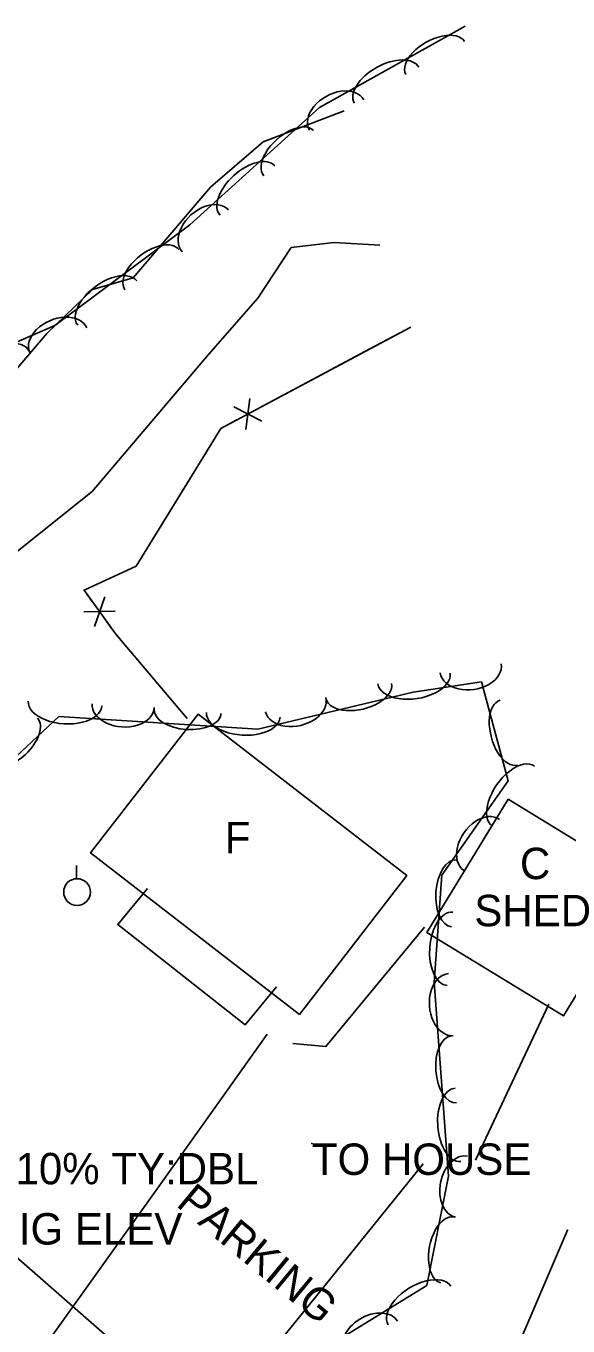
# Model space of a CAD drawing. Extents: x 1441650 to 1491889, y 345904 to 358319.
# Drawn here: x 1444391.3 to 1444477.5, y 355635.2 to 355842.2 of the extents above; entities that cross this region are included whole.
import ezdxf

# ---------------------------------------------------------------- set-up
doc = ezdxf.new("R2010")
doc.units = 0
for name, color, linetype in [('S_BUILDING', 7, 'Continuous'), ('S_BUILDING_ANNOT', 7, 'Continuous'), ('S_CROSS_DRAIN_ANNOT', 7, 'Continuous'), ('S_FENCE', 7, 'Continuous'), ('S_GRAVEL_ROAD', 7, 'Continuous'), ('S_MSC_PT_SYM', 7, 'Continuous'), ('S_PARKING', 7, 'Continuous'), ('S_PARKING_ANNOT', 7, 'Continuous'), ('S_SANITARY_SEWER', 7, 'Continuous'), ('S_SECONDARY_CTL_ANNOT', 7, 'Continuous'), ('S_SIDEWALK', 7, 'Continuous'), ('S_STREAM', 7, 'Continuous'), ('S_SURVEY_TEXT_ANNOT', 7, 'Continuous'), ('S_TREE', 7, 'Continuous'), ('S_UTILITY_POLE', 7, 'Continuous')]:
    doc.layers.add(name, color=color, linetype=linetype)

msp = doc.modelspace()

# ---------------------------------------------------------------- linework, layer by layer
at = {"layer": 'S_BUILDING'}
for points in [[(1444418.69, 355732.62), (1444451.91, 355706.91), (1444434.81, 355684.82), (1444401.59, 355710.53)], [(1444468.03, 355719.06), (1444489.77, 355705.76), (1444476.81, 355684.57), (1444455.07, 355697.86)]]:
    msp.add_lwpolyline(points, close=True, dxfattribs=at)
at = {"layer": 'S_FENCE'}
for p, q in [((1444426.3, 355777.92), (1444426.9, 355782.88)), ((1444424.37, 355781.53), (1444428.83, 355779.27)), ((1444402.2, 355746.58), (1444403.84, 355751.3)), ((1444405.51, 355748.99), (1444400.52, 355748.89)), ((1444477.43, 355650.46), (1444449.11, 355584.29))]:
    msp.add_line(p, q, dxfattribs=at)
for points in [[(1444416.95, 355731.95), (1444405.62, 355745.35), (1444400.54, 355752.36), (1444408.83, 355756.16), (1444422.3, 355778.11), (1444452.51, 355794.22)], [(1444446.01, 355790.76), (1444452.51, 355794.22)], [(1444428.37, 355781.35), (1444446.01, 355790.76)], [(1444413.34, 355763.52), (1444422.3, 355778.11), (1444424.84, 355779.46)], [(1444401.85, 355750.55), (1444400.54, 355752.36), (1444408.83, 355756.16), (1444413.34, 355763.52)], [(1444416.95, 355731.95), (1444405.62, 355745.35), (1444404.19, 355747.33)]]:
    msp.add_lwpolyline(points, dxfattribs=at)
at = {"layer": 'S_GRAVEL_ROAD'}
for points in [[(1444358.59, 355612.22), (1444371.41, 355616.19), (1444383.51, 355622.5), (1444395.16, 355633.2), (1444403.8, 355645.32), (1444412.43, 355657.43), (1444421.07, 355669.55), (1444429.7, 355681.67)], [(1444454.48, 355661.03), (1444439.8, 355642.84), (1444425.11, 355624.65), (1444410.77, 355628.2), (1444400.86, 355624.41), (1444394.09, 355619.51), (1444383.13, 355609.65), (1444378.74, 355594.44)]]:
    msp.add_lwpolyline(points, dxfattribs=at)
at = {"layer": 'S_MSC_PT_SYM'}
for points in [[(1444436.79, 355664.26), (1444436.79, 355664.31), (1444436.79, 355664.26), (1444436.74, 355664.26), (1444436.79, 355664.26), (1444436.79, 355664.21), (1444436.79, 355664.26), (1444436.84, 355664.26)], [(1444477.43, 355650.46), (1444477.43, 355650.51), (1444477.43, 355650.46), (1444477.38, 355650.46), (1444477.43, 355650.46), (1444477.43, 355650.41), (1444477.43, 355650.46), (1444477.48, 355650.46)]]:
    msp.add_lwpolyline(points, dxfattribs=at)
at = {"layer": 'S_PARKING'}
for points in [[(1444454.7, 355698.68), (1444439.01, 355679.71), (1444433.76, 355680.18)], [(1444462.8, 355661.63), (1444474.51, 355686.42)]]:
    msp.add_lwpolyline(points, dxfattribs=at)
at = {"layer": 'S_SANITARY_SEWER'}
msp.add_line((1444279.33, 355742.27), (1444417.64, 355621.87), dxfattribs=at)
at = {"layer": 'S_SIDEWALK'}
msp.add_lwpolyline([(1444431.17, 355689.19), (1444426.19, 355683.17), (1444405.9, 355699.12), (1444410.66, 355704.88)], dxfattribs=at)
at = {"layer": 'S_STREAM'}
for points in [[(1444441.93, 355828.65), (1444429.04, 355823.72), (1444420.65, 355816.52), (1444408.37, 355802.07), (1444401.88, 355800.24), (1444394.64, 355793.25), (1444389.5, 355787.19), (1444381.75, 355780.67), (1444366.63, 355772.48), (1444357.59, 355763.93), (1444355, 355760.85), (1444356.46, 355756.48), (1444352.71, 355749.61), (1444349.23, 355745.43)], [(1444362.43, 355740.87), (1444369.13, 355746.99), (1444380.64, 355751.13), (1444401.82, 355768.08), (1444408.39, 355775.83), (1444420.35, 355789.89), (1444428.21, 355798.87), (1444433.51, 355806.91), (1444440.33, 355807.72), (1444447.6, 355807.28)]]:
    msp.add_lwpolyline(points, dxfattribs=at)
at = {"layer": 'S_TREE'}
msp.add_lwpolyline([(1444439.99, 355632.37), (1444455.08, 355641.66), (1444458.51, 355659.06), (1444456.24, 355689.92), (1444457.49, 355706.97), (1444468, 355722.01), (1444463.75, 355737.74), (1444452.88, 355736.12), (1444428.18, 355730.23), (1444396.54, 355732.23), (1444378.65, 355715.51), (1444375.93, 355687.86), (1444361.42, 355675.31), (1444312.57, 355716.37), (1444299.15, 355732.14), (1444308.73, 355742.97), (1444326.15, 355747.23), (1444344.95, 355760.97), (1444363.61, 355780.49), (1444395.92, 355794.52), (1444417.37, 355810.55), (1444437.99, 355829.22), (1444461.16, 355842.18)], dxfattribs=at)
for centre, major_axis, ratio, start_param, end_param in [((1444456.4, 355837.09), (-4.66, -2.61), 0.540688, 3.141171, 6.282764), ((1444448.66, 355832.76), (-5.12, -2.87), 0.550068, 3.141158, 6.28275), ((1444440.71, 355828.02), (-4.32, -2.42), 0.685296, 3.14088, 6.282473), ((1444433.1, 355821.94), (-3.96, -3.59), 0.540609, 3.141581, 6.283174), ((1444426.53, 355815.98), (-4.35, -3.94), 0.549988, 3.141581, 6.283173), ((1444419.84, 355809.58), (-3.67, -3.33), 0.685196, 3.141573, 6.283166), ((1444411.33, 355803.39), (-4.28, -3.2), 0.540593, 3.141689, 6.283282), ((1444404.23, 355798.08), (-4.7, -3.51), 0.549971, 3.141692, 6.283285), ((1444396.44, 355792.15), (-4.54, -1.96), 0.686614, 3.143857, 6.28545), ((1444386.91, 355788.29), (-4.89, -2.12), 0.541728, 3.142929, 6.284522), ((1444462.07, 355739.9), (4.86, 0.71), 0.691552, 3.147158, 6.288751), ((1444444.26, 355736.24), (5.18, 1.23), 0.542491, 3.143528, 6.285121), ((1444453.04, 355738.29), (5.75, 0.85), 0.555094, 3.144961, 6.286554), ((1444434.22, 355734.12), (4.8, 1.13), 0.687579, 3.144876, 6.286469), ((1444397.53, 355734.3), (5.85, -0.37), 0.550441, 3.142829, 6.284422), ((1444406.77, 355733.97), (4.94, -0.32), 0.68576, 3.14362, 6.285213), ((1444417.03, 355733.06), (5.33, -0.34), 0.541055, 3.142791, 6.284383), ((1444468.13, 355729.66), (1.39, -5.16), 0.540913, 3.141986, 6.283579), ((1444389.24, 355728.32), (3.91, 3.65), 0.540627, 3.141692, 6.283284), ((1444425.87, 355732.5), (5.85, -0.37), 0.550441, 3.142829, 6.284422), ((1444468.87, 355719.55), (-3.36, -4.81), 0.550057, 3.141522, 6.283115), ((1444463.78, 355711.81), (-2.84, -4.06), 0.685283, 3.141477, 6.28307), ((1444459.4, 355704.1), (-0.39, -5.33), 0.541028, 3.141743, 6.283335), ((1444458.76, 355695.26), (-0.43, -5.85), 0.550415, 3.141748, 6.28334), ((1444458.89, 355686.36), (0.36, -4.94), 0.685282, 3.141652, 6.283245), ((1444459.39, 355676.06), (0.39, -5.33), 0.540677, 3.141628, 6.28322), ((1444460.03, 355667.22), (0.43, -5.85), 0.550057, 3.141629, 6.283221), ((1444460.6, 355657.39), (-0.96, -4.86), 0.68531, 3.141592, 6.283184), ((1444458.36, 355647.33), (-1.03, -5.25), 0.540699, 3.141592, 6.283185), ((1444453.93, 355638.46), (-4.99, -3.07), 0.550665, 3.142527, 6.28412), ((1444446.19, 355633.39), (-4.22, -2.59), 0.686039, 3.143125, 6.284717)]:
    msp.add_ellipse(centre, major_axis=major_axis, ratio=ratio, start_param=start_param, end_param=end_param, dxfattribs=at)
at = {"layer": 'S_UTILITY_POLE'}
msp.add_line((1444399.32, 355706.44), (1444399.32, 355708.54), dxfattribs=at)
msp.add_circle((1444399.44, 355704.29), 2.13, dxfattribs=at)

# ---------------------------------------------------------------- texts
at = {"layer": 'S_BUILDING_ANNOT'}
for s, p in [('F', (1444422.93, 355710.47)), ('C', (1444469.89, 355706.35)), ('SHED', (1444462.63, 355698.85))]:
    msp.add_text(s, height=5, dxfattribs=at).set_placement(p)
at = {"layer": 'S_CROSS_DRAIN_ANNOT'}
msp.add_text('WD:10.00 HT:6.00 CN:10% TY:DBL ', height=5, dxfattribs=at).set_placement((1444320.9, 355657.76))
at = {"layer": 'S_PARKING_ANNOT'}
msp.add_text('PARKING', height=5, rotation=320.3985, dxfattribs=at).set_placement((1444415.02, 355654.41))
at = {"layer": 'S_SECONDARY_CTL_ANNOT'}
msp.add_text('PD:SET 8" NAIL 1106 TRIG ELEV', height=5, dxfattribs=at).set_placement((1444313.85, 355648.17))
at = {"layer": 'S_SURVEY_TEXT_ANNOT'}
msp.add_text('TO HOUSE', height=5, dxfattribs=at).set_placement((1444436.79, 355659.26))

doc.saveas('drawing.dxf')
